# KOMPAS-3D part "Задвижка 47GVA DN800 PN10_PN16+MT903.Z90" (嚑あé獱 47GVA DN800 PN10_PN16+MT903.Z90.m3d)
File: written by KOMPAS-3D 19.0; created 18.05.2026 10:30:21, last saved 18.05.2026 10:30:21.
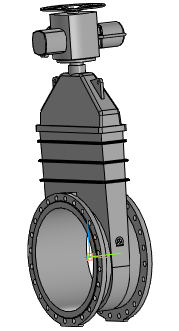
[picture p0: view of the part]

Document properties: Автор: Энергия; Полное имя файла: ..\Задвижка 47GVA DN40_DN1000+MT903.Z\Задвижка 47GVA DN800 PN10_PN16+MT903.Z90.a3d

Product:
- Part/product: Задвижка 47GVA DN800 PN10_PN16+MT903.Z90
    Масса: 2022.95
  - Body: Электропривод MT903.Z90-120
      Масса: 369.82
  - Body: Задвижка 47GVA DN800 PN10_PN16_F25 без исполнительного механизма
      Масса: 1653.13

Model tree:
1. Операция без истории:1
2. Операция без истории:2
